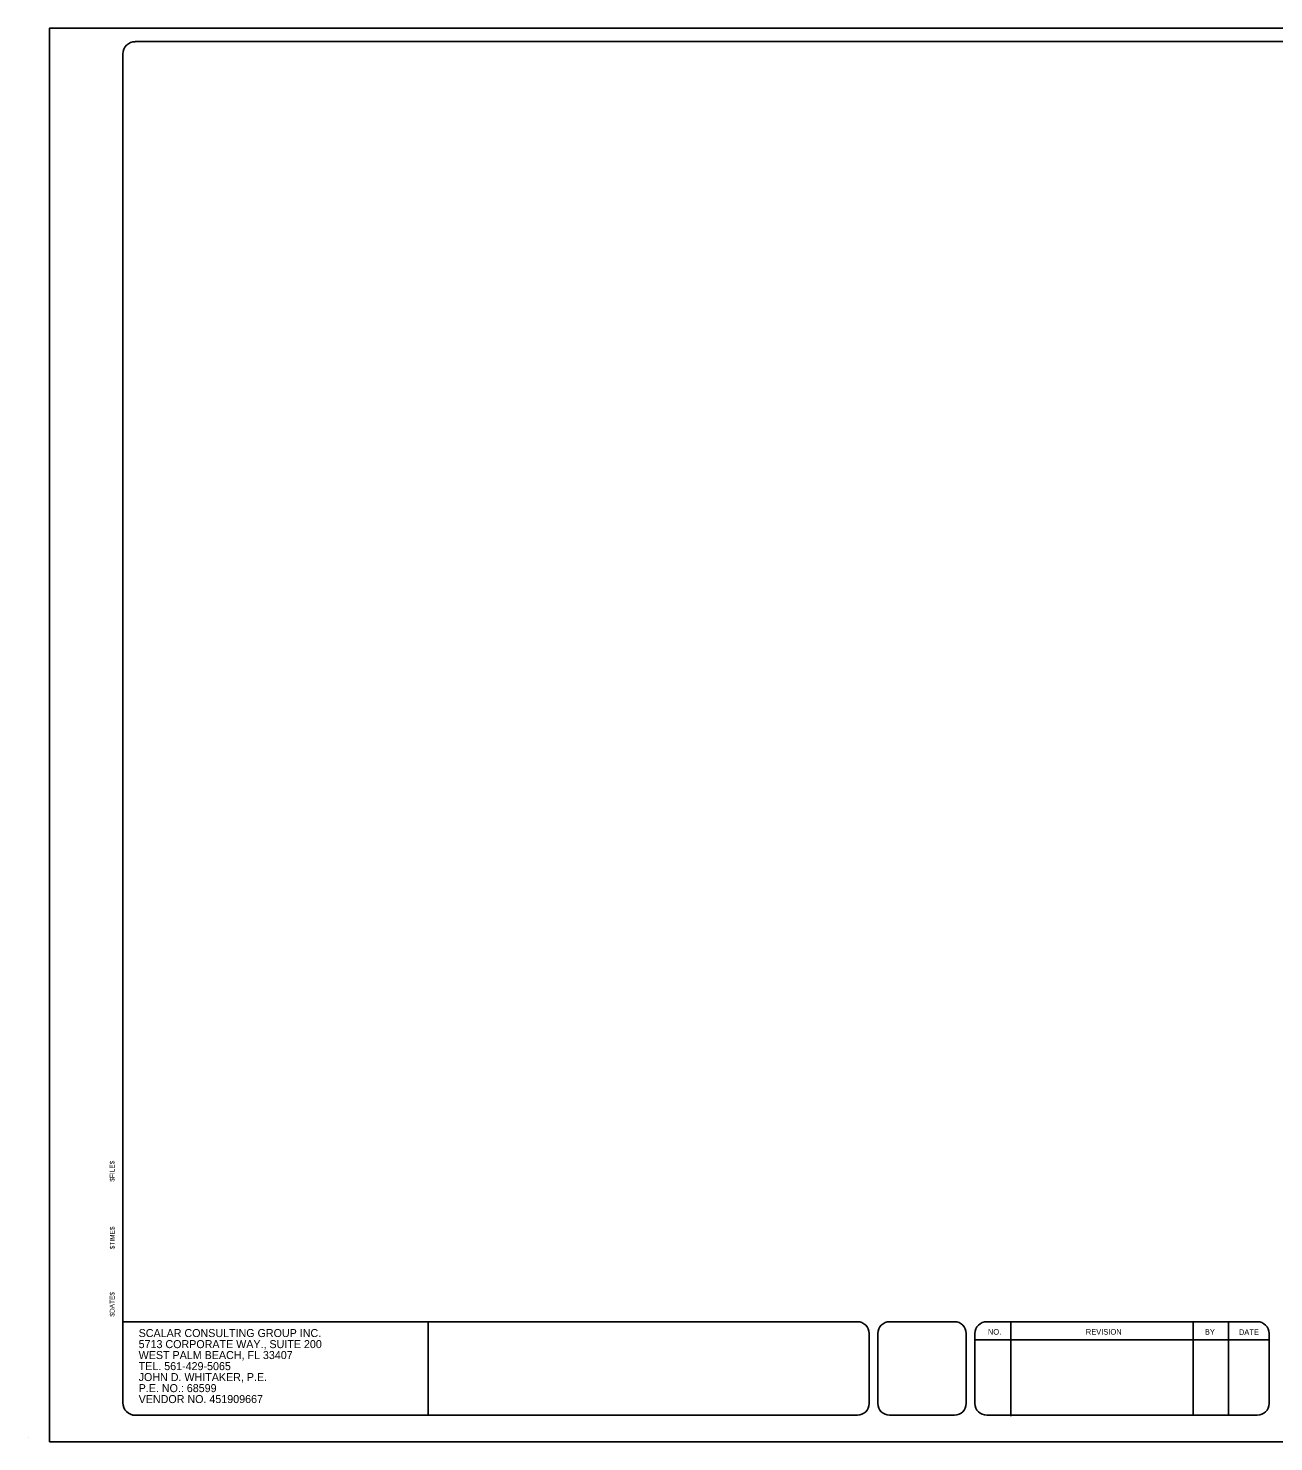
# Model space of a CAD drawing. Extents: x -0.7 to 16, y -0.9 to 9.7.
# Drawn here: x -0.71 to 8.63, y -0.9 to 9.7 of the extents above; entities that cross this region are included whole.
import ezdxf

# ---------------------------------------------------------------- set-up
doc = ezdxf.new("R2010")
doc.units = 0
for name, color, linetype in [('AdhocPoint_dp', 7, 'Continuous'), ('Default', 7, 'Continuous'), ('PlotBorder_dp', 7, 'Continuous')]:
    doc.layers.add(name, color=color, linetype=linetype)

msp = doc.modelspace()

# ---------------------------------------------------------------- linework, layer by layer
at = {"layer": 'AdhocPoint_dp'}
msp.add_line((-0.709, -0.87), (-0.709, -0.87), dxfattribs=at)
at = {"layer": 'Default'}
for p, q in [((15.325, 9.6), (0.094, 9.6)), ((0, -0.608), (0, 9.506)), ((5.508, 0), (0, 0)), ((6.236, 0), (5.75, 0)), ((8.507, 0), (6.478, 0)), ((2.289, -0.701), (2.289, 0)), ((5.596, -0.088), (5.596, -0.613)), ((5.662, -0.088), (5.662, -0.613)), ((6.324, -0.088), (6.324, -0.613)), ((6.39, -0.088), (6.39, -0.613)), ((6.658, -0.004), (6.658, -0.709)), ((8.025, -0.004), (8.025, -0.7)), ((8.29, -0.004), (8.29, -0.7)), ((8.595, -0.088), (8.595, -0.613)), ((8.599, -0.136), (6.393, -0.136)), ((5.508, -0.701), (0.093, -0.701)), ((6.236, -0.701), (5.75, -0.701)), ((8.507, -0.701), (6.478, -0.701))]:
    msp.add_line(p, q, dxfattribs=at)
for centre, major_axis, start_param, end_param in [((0.094, 9.506), (0, -0.0935), 3.141593, 4.712389), ((5.508, -0.088), (0, 0.0882), 4.712389, 6.283185), ((5.75, -0.088), (0, 0.0882), 0, 1.570796), ((6.236, -0.088), (0, 0.0882), 4.712389, 6.283185), ((6.478, -0.088), (0, 0.0882), 0, 1.570796), ((8.507, -0.088), (0, 0.0882), 4.712389, 6.283185), ((0.094, -0.608), (0, -0.0935), 4.712389, 6.283185), ((5.508, -0.613), (0, 0.0882), 3.141593, 4.712389), ((5.75, -0.613), (0, -0.0882), 4.712389, 6.283185), ((6.236, -0.613), (0, 0.0882), 3.141593, 4.712389), ((6.478, -0.613), (0, -0.0882), 4.712389, 6.283185), ((8.507, -0.613), (0, 0.0882), 3.141593, 4.712389)]:
    msp.add_ellipse(centre, major_axis=major_axis, ratio=0.999927, start_param=start_param, end_param=end_param, dxfattribs=at)
at = {"layer": 'PlotBorder_dp'}
msp.add_lwpolyline([(-0.55, -0.9), (15.95, -0.9), (15.95, 9.7), (-0.55, 9.7)], close=True, dxfattribs=at)

# ---------------------------------------------------------------- texts
at = {"layer": 'Default'}
for s, p in [('$FILE$', (-0.062, 1.05)), ('$TIME$', (-0.061, 0.543)), ('$DATE$', (-0.062, 0.038))]:
    msp.add_text(s, height=0.0354, rotation=90, dxfattribs=at).set_placement(p)
for s, height, p in [('SCALAR CONSULTING GROUP INC.', 0.06, (0.119, -0.115)), ('NO.', 0.0421, (6.487, -0.097)), ('REVISION', 0.0421, (7.221, -0.097)), ('BY', 0.0421, (8.114, -0.097)), ('DATE', 0.0421, (8.369, -0.099)), ('5713 CORPORATE WAY., SUITE 200', 0.06, (0.119, -0.198)), ('WEST PALM BEACH, FL 33407', 0.06, (0.119, -0.28)), ('TEL. 561-429-5065', 0.06, (0.119, -0.363)), ('JOHN D. WHITAKER, P.E.', 0.06, (0.119, -0.445)), ('P.E. NO.: 68599', 0.06, (0.119, -0.528)), ('VENDOR NO. 451909667', 0.06, (0.119, -0.61))]:
    msp.add_text(s, height=height, dxfattribs=at).set_placement(p)

doc.saveas('drawing.dxf')
